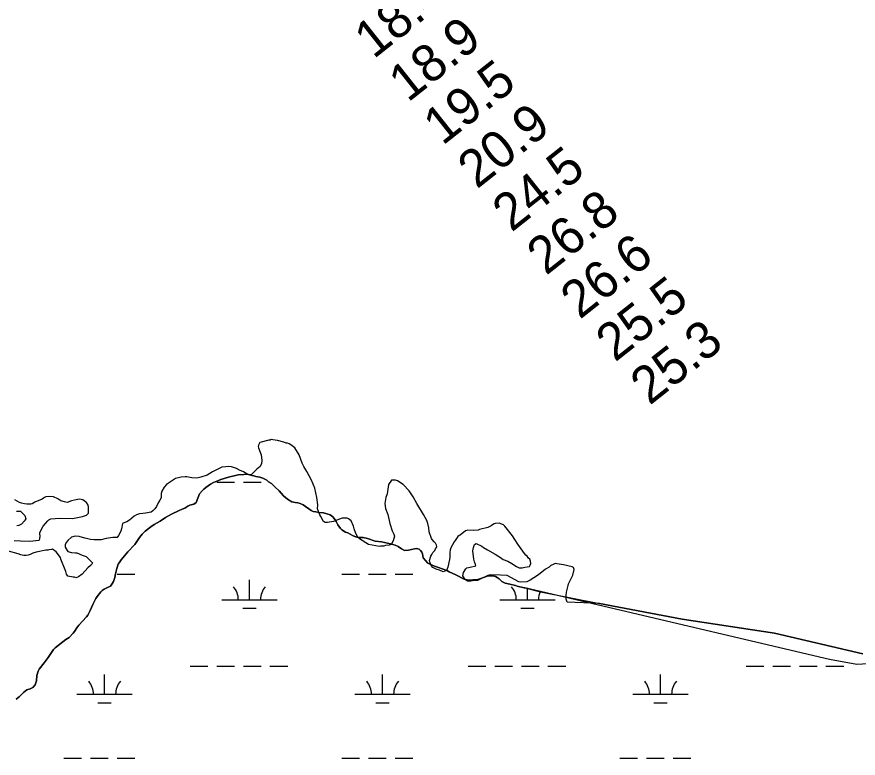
# Model space of a CAD drawing. Extents: x 3192927 to 3230760, y 831141 to 856475.
# Drawn here: x 3205435 to 3206954, y 845280 to 846620 of the extents above; entities that cross this region are included whole.
import ezdxf

# ---------------------------------------------------------------- set-up
doc = ezdxf.new("R2010")
doc.units = 0
for name, color, linetype in [('V-RIVR-RANG', 7, 'Continuous'), ('V-SITE-VEGE', 7, 'Continuous'), ('V-TOPO-SHOR', 7, 'Continuous'), ('V-WETL-SWMP', 7, 'Continuous')]:
    doc.layers.add(name, color=color, linetype=linetype)

msp = doc.modelspace()

# ---------------------------------------------------------------- linework, layer by layer
at = {"layer": 'V-SITE-VEGE'}
for points in [[(3206218.9, 845660.3), (3206217.8, 845656.3), (3206217.2, 845651.9), (3206217.5, 845643.5), (3206216.4, 845639), (3206213.6, 845625.3), (3206211, 845619.4), (3206208.5, 845618), (3206205, 845617), (3206198.6, 845619.7), (3206192.7, 845621.3), (3206186.3, 845624.4), (3206183.5, 845628), (3206181.1, 845634.9), (3206180.7, 845636.9), (3206182.9, 845644.8), (3206184.9, 845648.2), (3206186.5, 845651.6), (3206190.1, 845655.5), (3206191.6, 845658.5), (3206193.1, 845660.4), (3206193.7, 845662.4), (3206193.2, 845664.8), (3206191.4, 845668.4), (3206188.9, 845670.9), (3206185.6, 845675.4), (3206184.1, 845676.9), (3206180, 845688.9), (3206179.2, 845696.4), (3206177.4, 845704.3), (3206176, 845709.3), (3206169.8, 845720.3), (3206157.5, 845740.4), (3206150.8, 845752), (3206143.6, 845763.1), (3206133, 845774.7), (3206122.8, 845781.4), (3206118.9, 845782.5), (3206114.4, 845782.6), (3206111.9, 845782.1), (3206106.3, 845774.8), (3206103.9, 845757.6), (3206101.8, 845751.2), (3206100, 845740.3), (3206101.3, 845731.4), (3206105.5, 845720.4), (3206109.1, 845704), (3206113.2, 845690.5), (3206116, 845685), (3206117.4, 845681), (3206116.3, 845677.1), (3206114.7, 845672.7), (3206111.1, 845665.8), (3206107.6, 845664.9), (3206101.2, 845664.1), (3206098.2, 845663.2), (3206092.7, 845662.8), (3206090.2, 845662.4), (3206070.5, 845665.8), (3206053.9, 845676.1), (3206051, 845679.2), (3206047.3, 845686.2), (3206044.5, 845694.2), (3206043.1, 845699.1), (3206038.9, 845709.1), (3206034.5, 845712.7), (3206032.1, 845713.8), (3206026.6, 845713.9), (3206022.7, 845713.5), (3206013.2, 845710.3), (3206007.2, 845707.9), (3205996.2, 845705.7), (3205992.3, 845705.8), (3205988.9, 845707.9), (3205984.1, 845716.4), (3205982.7, 845719.4), (3205979.9, 845725.9), (3205978.5, 845730.4), (3205979.2, 845737.8), (3205977, 845751.2), (3205973.5, 845768.1), (3205967.4, 845782.6), (3205958.9, 845798.2), (3205953.6, 845807.2), (3205950.8, 845813.2), (3205945.2, 845828.2), (3205937.1, 845840.8), (3205930.3, 845846.4), (3205926.9, 845848), (3205924, 845849), (3205921.5, 845849.1), (3205917.6, 845850.7), (3205906.3, 845853.9), (3205897.4, 845855.1), (3205894.9, 845855.7), (3205892.9, 845854.7), (3205890.4, 845854.8), (3205874, 845850.2), (3205871.9, 845845.3), (3205871.4, 845842.9), (3205871.8, 845840.9)], [(3205871.8, 845840.9), (3205876.9, 845827.9), (3205877.7, 845818), (3205877.1, 845812.5), (3205874.5, 845807.1), (3205871.9, 845804.7), (3205868.9, 845802.3), (3205858.3, 845792.2), (3205852.8, 845792.8), (3205844.5, 845797.5), (3205837.2, 845800.6), (3205832.3, 845803.2), (3205823, 845806.4), (3205818.5, 845807), (3205812.6, 845806.7), (3205805.6, 845805.8), (3205803.1, 845804.4), (3205788.6, 845797.3), (3205779, 845791.6), (3205767.6, 845787.9), (3205760.6, 845786.1), (3205751.7, 845786.3), (3205742.3, 845788.5), (3205739.4, 845788.6), (3205732.4, 845787.8), (3205729.9, 845787.4), (3205722, 845785.6), (3205705.9, 845774.6), (3205701.3, 845769.7), (3205697.2, 845762.4), (3205696.1, 845758), (3205695.9, 845750.6), (3205693.8, 845746.2), (3205690.7, 845741.3), (3205687.6, 845734.9), (3205684.5, 845730.5), (3205681, 845727.2), (3205678, 845724.8), (3205668, 845722.5), (3205663, 845722.1), (3205657.1, 845721.3), (3205651.6, 845719.5), (3205647.1, 845717.1), (3205639, 845709.9), (3205634, 845707), (3205630.5, 845706.1), (3205626.5, 845704.2), (3205624.3, 845694.4), (3205623.2, 845690.4), (3205619, 845682.1), (3205616.5, 845678.7), (3205608.5, 845678.9), (3205596.6, 845676.7), (3205587.6, 845674.5), (3205574.8, 845674.3), (3205568.4, 845674.9), (3205561, 845677.1), (3205558, 845677.6), (3205548.2, 845680.4), (3205540.8, 845681), (3205534.3, 845679.2), (3205527.7, 845673.4), (3205524.7, 845670), (3205522.6, 845665.6), (3205523, 845661.2), (3205526.3, 845655.2), (3205527.8, 845653.6), (3205534.1, 845651.5), (3205541.5, 845650.8), (3205544, 845650.8), (3205553.3, 845647.1), (3205555.3, 845646.5), (3205560.7, 845644.4), (3205571.8, 845632.8), (3205570.8, 845630.8), (3205568.7, 845628.4), (3205563.7, 845624.1), (3205553.5, 845612.4), (3205546.9, 845607.6), (3205543.9, 845606.2), (3205541.9, 845605.8), (3205539.5, 845606.8), (3205537, 845606.9), (3205527.7, 845609.1), (3205525.3, 845612.6), (3205523.9, 845617.1), (3205522.5, 845620.1), (3205515, 845639.6), (3205514.1, 845642.6), (3205506.4, 845652.7), (3205500.1, 845657.8), (3205498.1, 845656.8), (3205493.2, 845656.4), (3205491.2, 845656), (3205487.7, 845656.1), (3205470.3, 845652.5), (3205464.3, 845650.7), (3205459.8, 845648.3), (3205455.8, 845646.9), (3205452.3, 845646), (3205448.4, 845646.1)], [(3205430.7, 845673.3), (3205442.1, 845672.5), (3205458.4, 845672.1), (3205475.8, 845674.2), (3205477.3, 845676.6), (3205477.4, 845681.6), (3205477, 845684.5), (3205477.1, 845688), (3205482.8, 845699.3), (3205491.5, 845708.9), (3205493, 845710.4), (3205497, 845712.3), (3205512.4, 845713.9), (3205536.1, 845713.3), (3205554, 845716.4), (3205561.5, 845719.1), (3205563, 845720.6), (3205564.6, 845723), (3205564.8, 845734.4), (3205564.4, 845737.4), (3205561.1, 845741.9), (3205559.6, 845743.4), (3205554.7, 845746.5), (3205548.8, 845747.7), (3205539.4, 845746.4), (3205534.4, 845745), (3205526.4, 845741.8), (3205521.5, 845742.9), (3205515.1, 845745), (3205513.1, 845746), (3205509.7, 845748.6), (3205501.9, 845752.3), (3205494, 845752.9), (3205488, 845752.1), (3205485.6, 845751.2), (3205483.5, 845749.7), (3205481, 845748.3), (3205468, 845742.7), (3205463, 845739.8), (3205460.5, 845738.9), (3205453.6, 845739.1), (3205449.6, 845739.7), (3205444.2, 845740.8), (3205440.3, 845741.9), (3205432, 845746.5)], [(3205435, 845726.1), (3205441.9, 845726.5), (3205450.1, 845718.4), (3205451.5, 845712.4), (3205450.4, 845710.4), (3205448.9, 845708), (3205443.8, 845702.7), (3205438.8, 845700.3), (3205435.3, 845699.9)], [(3206962.7, 845468.3), (3206803.6, 845505.8), (3206636.8, 845531.4), (3206487.2, 845559.6), (3206428.8, 845561.7), (3206427.5, 845567.6), (3206427.2, 845574.1), (3206427.8, 845580), (3206430.6, 845592.3), (3206431.6, 845594.8), (3206439.4, 845610.4), (3206441.7, 845620.8), (3206440.3, 845624.8), (3206438.3, 845625.8), (3206422.6, 845629.6), (3206410.7, 845631.4), (3206407.3, 845631.5), (3206403.8, 845630.1), (3206399.8, 845628.2), (3206396.7, 845625.3), (3206390.2, 845621.5), (3206377.1, 845611.4), (3206369, 845605.7), (3206362.5, 845601.4), (3206356, 845598.6), (3206344.6, 845597.9), (3206342.1, 845598.9), (3206320.6, 845609.8), (3206308.8, 845610.6), (3206290.9, 845611), (3206286, 845610.1), (3206267, 845601.2), (3206261, 845600.9), (3206255, 845600), (3206249.1, 845600.1), (3206245.2, 845602.7), (3206240.4, 845609.3), (3206242, 845615.2), (3206246.2, 845622), (3206248.2, 845623.9), (3206250.7, 845624.4), (3206253.7, 845625.3), (3206264.1, 845627.5), (3206263.7, 845630), (3206261.8, 845634.5), (3206260.5, 845639.5), (3206258.8, 845654.9), (3206260, 845660.8), (3206261.6, 845666.2), (3206264.6, 845667.6), (3206274.9, 845662.9), (3206277.8, 845660.8), (3206285.1, 845656.2), (3206299.3, 845648.4), (3206308.5, 845642.8), (3206313.4, 845639.2), (3206321.7, 845636), (3206329.1, 845631.9), (3206337.8, 845626.2), (3206342.7, 845624.1), (3206347.7, 845624), (3206352.7, 845625.4), (3206361.1, 845626.2), (3206362.2, 845628.6), (3206363.2, 845631.6), (3206362.8, 845636), (3206361.4, 845639.5), (3206359.5, 845641.5), (3206356.6, 845645.1), (3206354.7, 845646.6), (3206351.8, 845650.1), (3206339.8, 845666.8), (3206334.6, 845675.3), (3206330.3, 845681.8), (3206316.8, 845699), (3206313.9, 845701.5), (3206306.1, 845704.7), (3206299.1, 845703.9), (3206297.1, 845703.4), (3206294.1, 845701.5), (3206291.6, 845699.6), (3206286.1, 845696.8), (3206270.7, 845693.2), (3206268.2, 845692.2), (3206260.2, 845691.4), (3206249.8, 845691.7), (3206245.8, 845690.8), (3206235.8, 845683.1), (3206233.8, 845682.2), (3206231.7, 845680.8), (3206226.6, 845673.4), (3206225.1, 845671), (3206218.9, 845660.3)], [(3205448.4, 845646.1), (3205444.9, 845646.7), (3205443, 845647.3), (3205438.1, 845649.4), (3205420.4, 845654.2)]]:
    msp.add_lwpolyline(points, dxfattribs=at)
at = {"layer": 'V-TOPO-SHOR'}
for points in [[(3205587, 845580.3), (3205589.6, 845582.9), (3205593.1, 845585.3), (3205599.2, 845588.4), (3205604.6, 845591), (3205608.2, 845596), (3205610.1, 845599.5), (3205612.6, 845606.7), (3205613.6, 845613), (3205615.9, 845623), (3205618.7, 845630.6), (3205620.2, 845633.2), (3205623.8, 845638.1), (3205636.1, 845653), (3205648.4, 845666.3), (3205656.7, 845678.9), (3205661.8, 845684.8), (3205667.3, 845690.2), (3205677.2, 845698), (3205683.2, 845702.2), (3205694.1, 845708.5), (3205703.7, 845714.8), (3205714.8, 845720.8), (3205728.5, 845727.6), (3205734.2, 845729.8), (3205738.5, 845731.7), (3205744.2, 845735.1), (3205747.9, 845737.1), (3205755.2, 845739.1), (3205759, 845742.1), (3205765.1, 845757.9), (3205769.8, 845763.1), (3205773.1, 845766.1), (3205776.7, 845769.1), (3205784.9, 845774.9), (3205790.7, 845778), (3205799.7, 845781.9), (3205803.8, 845783.5), (3205817.7, 845787.9), (3205835.1, 845791.8), (3205845.2, 845792.8), (3205850, 845793.1), (3205853.5, 845792.6), (3205860, 845790.8), (3205863.3, 845790.3), (3205867.2, 845789.2), (3205874.2, 845788), (3205879.5, 845786.2), (3205886.8, 845782.1), (3205890, 845779.6), (3205895.1, 845776.1), (3205898.3, 845773.4), (3205902.1, 845769.8), (3205909.2, 845762.8), (3205917.2, 845754.2), (3205924.1, 845748.1), (3205932.2, 845743.3), (3205938.1, 845742.2), (3205943.1, 845741.4), (3205946.9, 845740.3), (3205952.4, 845737.5), (3205966.8, 845727.5), (3205970.5, 845725.9), (3205975.4, 845725), (3205980.9, 845724.2), (3205989.2, 845723.6), (3206001, 845719.6), (3206005.9, 845716), (3206008.3, 845712.9), (3206012.1, 845707.4), (3206014.8, 845701.8), (3206019.8, 845694.9), (3206022.2, 845692.6), (3206028.9, 845688.5), (3206033, 845686.9), (3206041.3, 845682.6), (3206045.6, 845680.7), (3206049.5, 845679.6), (3206053.6, 845679), (3206060.6, 845678.5), (3206068.6, 845677), (3206082.3, 845672.4), (3206093.8, 845670.7), (3206099.1, 845669.7), (3206109.9, 845667), (3206118.5, 845665.1), (3206124.2, 845662.5), (3206129.9, 845658.1), (3206135.4, 845655.2), (3206142.8, 845655.7), (3206153.6, 845658.3), (3206157.3, 845658.6), (3206161.6, 845657.5), (3206164.4, 845655), (3206166.4, 845652), (3206168, 845649.3), (3206169.3, 845641.9), (3206177.3, 845632.4), (3206184.4, 845629.1), (3206189.7, 845627), (3206194.8, 845625.4)], [(3206194.8, 845625.4), (3206205.2, 845621.8), (3206213, 845618.4), (3206215.8, 845616.6), (3206227.8, 845611), (3206243.3, 845603.4), (3206250.9, 845601.6), (3206258.7, 845602.2), (3206265.7, 845602.5), (3206271.1, 845604.2), (3206278, 845606.7), (3206286.3, 845609.4), (3206290.4, 845609.7), (3206294.7, 845609.4), (3206299.4, 845608.5), (3206302.5, 845606.7), (3206306.1, 845603.8), (3206311.4, 845599.1), (3206317, 845596.1), (3206325.3, 845594.7), (3206335.7, 845591.9), (3206338.5, 845590.8), (3206351.6, 845587.6), (3206352.5, 845587.6)], [(3205434.5, 845386.7), (3205439.5, 845390.9), (3205441.9, 845393.1), (3205447.4, 845398.9), (3205453.4, 845403.7), (3205459.5, 845405.6), (3205464.5, 845407.8), (3205468.7, 845412.8), (3205470.7, 845419.6), (3205471.6, 845429.6), (3205474.2, 845437.2), (3205476, 845440.7), (3205484.9, 845452.2), (3205492.1, 845462.1), (3205501.5, 845476.3), (3205504.5, 845479.1), (3205524.2, 845494.5), (3205529.9, 845498.3), (3205537.2, 845505.7), (3205539.8, 845509.1), (3205543.7, 845515.8), (3205547.3, 845520.3), (3205561.2, 845535.6), (3205563.6, 845538.6), (3205567.9, 845546.6), (3205572.9, 845557.8), (3205578.3, 845568.3), (3205580.4, 845572.2), (3205587, 845580.3)], [(3206352.5, 845587.6), (3206381.1, 845580.5), (3206487.2, 845559.6), (3206636.8, 845531.4), (3206803.6, 845505.8), (3206962.7, 845468.3)]]:
    msp.add_lwpolyline(points, dxfattribs=at)
at = {"layer": 'V-WETL-SWMP'}
for p, q in [((3205796.5, 845778.8), (3205828.5, 845778.8)), ((3205844.5, 845778.8), (3205876.5, 845778.8)), ((3205616.5, 845612.7), (3205648.5, 845612.7)), ((3206022.4, 845612.7), (3206054.4, 845612.7)), ((3206070.4, 845612.7), (3206102.4, 845612.7)), ((3206118.4, 845612.7), (3206150.4, 845612.7)), ((3205855.3, 845566.2), (3205855.3, 845602.2)), ((3206357.2, 845566.2), (3206357.2, 845586.5)), ((3205805.3, 845566.2), (3205905.3, 845566.2)), ((3206307.2, 845566.2), (3206407.2, 845566.2)), ((3205843.3, 845550.8), (3205867.3, 845550.8)), ((3206345.2, 845550.8), (3206369.2, 845550.8)), ((3205748.5, 845446.2), (3205780.5, 845446.2)), ((3205796.5, 845446.2), (3205828.5, 845446.2)), ((3205844.5, 845446.2), (3205876.5, 845446.2)), ((3205892.5, 845446.2), (3205924.5, 845446.2)), ((3206250.4, 845446.2), (3206282.4, 845446.2)), ((3206298.4, 845446.2), (3206330.4, 845446.2)), ((3206346.4, 845446.2), (3206378.4, 845446.2)), ((3206394.4, 845446.2), (3206426.4, 845446.2)), ((3206752.3, 845446.2), (3206784.3, 845446.2)), ((3206800.3, 845446.2), (3206832.3, 845446.2)), ((3206848.3, 845446.2), (3206880.3, 845446.2)), ((3206896.3, 845446.2), (3206928.3, 845446.2)), ((3205593.9, 845395.4), (3205593.9, 845431.4)), ((3206095.8, 845395.4), (3206095.8, 845431.4)), ((3206597.7, 845395.4), (3206597.7, 845431.4)), ((3205543.9, 845395.4), (3205643.9, 845395.4)), ((3206045.8, 845395.4), (3206145.8, 845395.4)), ((3206547.7, 845395.4), (3206647.7, 845395.4)), ((3205581.9, 845380), (3205605.9, 845380)), ((3206083.8, 845380), (3206107.8, 845380)), ((3206585.7, 845380), (3206609.7, 845380)), ((3205520.5, 845280), (3205552.5, 845280)), ((3205568.5, 845280), (3205600.5, 845280)), ((3205616.5, 845280), (3205648.5, 845280)), ((3206022.4, 845280), (3206054.4, 845280)), ((3206070.4, 845280), (3206102.4, 845280)), ((3206118.4, 845280), (3206150.4, 845280)), ((3206524.3, 845280), (3206556.3, 845280)), ((3206572.3, 845280), (3206604.3, 845280)), ((3206620.3, 845280), (3206652.3, 845280))]:
    msp.add_line(p, q, dxfattribs=at)
for points in [[(3205845.2, 845792.8), (3205835.1, 845791.8), (3205817.7, 845787.9), (3205803.8, 845783.5), (3205799.7, 845781.9), (3205790.7, 845778), (3205784.9, 845774.9), (3205776.7, 845769.1), (3205773.1, 845766.1), (3205769.8, 845763.1), (3205765.1, 845757.8), (3205759, 845742.1), (3205755.2, 845739.1), (3205747.9, 845737.1), (3205744.2, 845735.1), (3205738.5, 845731.7), (3205734.2, 845729.8), (3205728.5, 845727.6), (3205714.8, 845720.8), (3205703.7, 845714.8), (3205694.1, 845708.5), (3205683.2, 845702.2), (3205677.2, 845698), (3205667.3, 845690.2), (3205661.8, 845684.8), (3205656.7, 845678.9), (3205648.4, 845666.3), (3205636.1, 845653), (3205623.8, 845638.1), (3205620.2, 845633.2), (3205618.7, 845630.6), (3205615.9, 845623), (3205613.6, 845613), (3205612.6, 845606.7), (3205610.1, 845599.5), (3205608.2, 845596), (3205604.6, 845591), (3205599.2, 845588.4), (3205593.1, 845585.3), (3205589.6, 845582.9), (3205587, 845580.3), (3205580.4, 845572.2), (3205578.3, 845568.3), (3205572.9, 845557.8), (3205567.9, 845546.6), (3205563.6, 845538.6), (3205561.2, 845535.6), (3205547.3, 845520.3), (3205543.7, 845515.8), (3205539.8, 845509.1), (3205537.2, 845505.7), (3205529.9, 845498.3), (3205524.2, 845494.5), (3205504.5, 845479.1), (3205501.5, 845476.3), (3205492.1, 845462.1), (3205484.9, 845452.2), (3205476, 845440.7), (3205474.2, 845437.2), (3205471.6, 845429.6), (3205470.7, 845419.6), (3205468.7, 845412.8), (3205464.5, 845407.8), (3205459.5, 845405.6), (3205453.4, 845403.7), (3205447.4, 845398.9), (3205441.9, 845393.1), (3205439.5, 845390.9), (3205434.5, 845386.7)], [(3206982.8, 845451.2), (3206951.9, 845449), (3206902.7, 845458.1), (3206352.5, 845587.6), (3206351.6, 845587.6), (3206338.5, 845590.8), (3206335.7, 845591.9), (3206325.3, 845594.7), (3206317, 845596.1), (3206311.4, 845599.1), (3206306.1, 845603.8), (3206302.5, 845606.7), (3206299.4, 845608.5), (3206294.7, 845609.4), (3206290.4, 845609.7), (3206286.3, 845609.4), (3206278, 845606.7), (3206271.1, 845604.2), (3206265.7, 845602.5), (3206258.7, 845602.2), (3206250.9, 845601.6), (3206243.3, 845603.4), (3206227.8, 845611), (3206215.8, 845616.6), (3206213, 845618.4), (3206205.2, 845621.8), (3206194.8, 845625.4), (3206189.7, 845627), (3206184.4, 845629.1), (3206177.3, 845632.4), (3206169.3, 845641.9), (3206168, 845649.3), (3206166.4, 845652), (3206164.4, 845655), (3206161.6, 845657.5), (3206157.3, 845658.6), (3206153.6, 845658.3), (3206142.8, 845655.7), (3206135.4, 845655.2), (3206129.9, 845658.1), (3206124.2, 845662.5), (3206118.5, 845665.1), (3206109.9, 845667), (3206099.1, 845669.7), (3206093.8, 845670.7), (3206082.3, 845672.4), (3206068.6, 845677), (3206060.6, 845678.5), (3206053.6, 845679), (3206049.5, 845679.5), (3206045.6, 845680.7), (3206041.3, 845682.6), (3206033, 845686.9), (3206028.9, 845688.5), (3206022.2, 845692.6), (3206019.8, 845694.9), (3206014.8, 845701.8), (3206012.1, 845707.4), (3206008.3, 845712.9), (3206005.9, 845716), (3206001, 845719.6), (3205989.2, 845723.6), (3205980.9, 845724.2), (3205975.4, 845725), (3205970.5, 845725.9), (3205966.8, 845727.5), (3205952.4, 845737.5), (3205946.9, 845740.3), (3205943.1, 845741.4), (3205938.1, 845742.2), (3205932.2, 845743.3), (3205924.1, 845748.1), (3205917.2, 845754.2), (3205909.2, 845762.8), (3205902.1, 845769.8), (3205898.3, 845773.4), (3205895.1, 845776.1), (3205890, 845779.6), (3205886.8, 845782.1), (3205879.5, 845786.2), (3205874.2, 845788), (3205867.2, 845789.2), (3205863.3, 845790.3), (3205860, 845790.8), (3205853.5, 845792.6), (3205850, 845793.1), (3205845.2, 845792.8)]]:
    msp.add_lwpolyline(points, dxfattribs=at)
for centre, start, end in [((3205800.1, 845566.7), 359.2282, 40.7718), ((3205910.6, 845566.7), 139.2282, 180.7718), ((3206302, 845566.7), 359.2282, 40.7718), ((3206412.5, 845566.7), 155.9832, 180.7718), ((3205538.6, 845395.9), 359.2282, 40.7718), ((3205649.1, 845395.9), 139.2282, 180.7718), ((3206040.5, 845395.9), 359.2282, 40.7718), ((3206151, 845395.9), 139.2282, 180.7718), ((3206542.4, 845395.9), 359.2282, 40.7718), ((3206652.9, 845395.9), 139.2282, 180.7718)]:
    msp.add_arc(centre, 35.2, start, end, dxfattribs=at)

# ---------------------------------------------------------------- texts
at = {"layer": 'V-RIVR-RANG'}
for s, p in [('18.4', (3206079.5, 846542.2)), ('18.9', (3206141.5, 846463.8)), ('19.5', (3206204, 846385.8)), ('20.9', (3206266.1, 846307.4)), ('24.5', (3206328.6, 846229.3)), ('26.8', (3206390.9, 846151.1)), ('26.6', (3206451.8, 846071.7)), ('25.5', (3206515.5, 845994.6)), ('25.3', (3206577.8, 845916.4))]:
    msp.add_text(s, height=67, rotation=38.3883, dxfattribs=at).set_placement(p)

doc.saveas('drawing.dxf')
